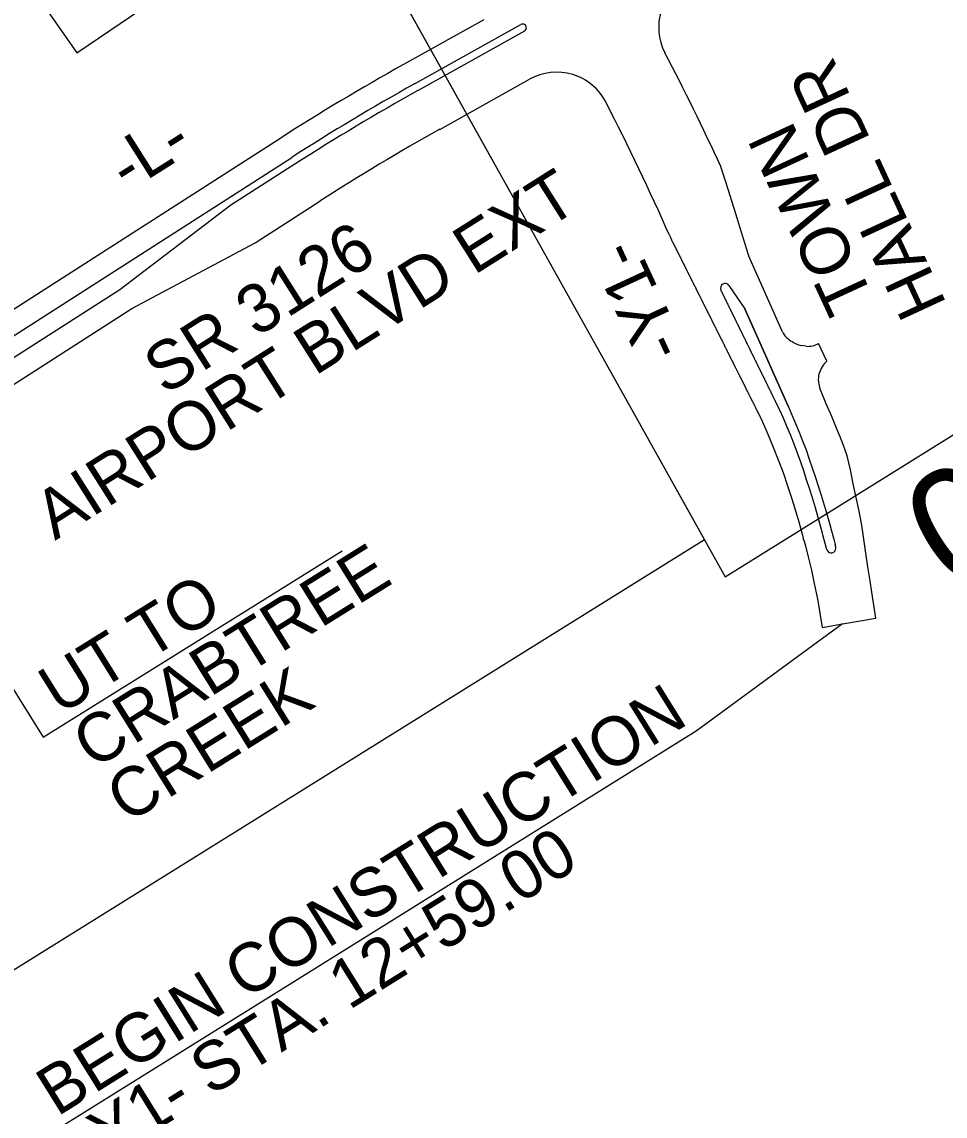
# Model space of a CAD drawing. Extents: x 2038094 to 2053858, y 751760 to 764312.
# Drawn here: x 2046894 to 2047889, y 757655 to 758834 of the extents above; entities that cross this region are included whole.
import ezdxf

# ---------------------------------------------------------------- set-up
doc = ezdxf.new("R2010")
doc.units = 0
for name, color, linetype in [('Old_Level_14', 7, 'Continuous'), ('Prop Shade Light', 7, 'Continuous'), ('Scratch_Level_1', 7, 'Continuous'), ('Sheet Data Field CELL', 7, 'Continuous')]:
    doc.layers.add(name, color=color, linetype=linetype)

msp = doc.modelspace()

# ---------------------------------------------------------------- linework, layer by layer
at = {"layer": 'Old_Level_14'}
for points in [[(2046826.6, 758207.9), (2046916.9, 758063.2), (2047239.3, 758264)], [(2047778.5, 758185.1), (2047620.9, 758069.4), (2046917.9, 757631.6)]]:
    msp.add_lwpolyline(points, dxfattribs=at)
at = {"layer": 'Prop Shade Light'}
for p, q in [((2047392, 758836.5), (2047305.4, 758788.2)), ((2047317.1, 758767.2), (2047431.9, 758831.3)), ((2047435.8, 758824.3), (2047321, 758760.2)), ((2047344.4, 758718.3), (2047441, 758772.3)), ((2047171.9, 758708.2), (2046658.7, 758379)), ((2046689.7, 758370.3), (2047184.9, 758688)), ((2047189.2, 758681.3), (2047119.4, 758636.5)), ((2047647.3, 758678.3), (2047647.3, 758678.3)), ((2047119.4, 758636.5), (2046999.6, 758545.4)), ((2047145.3, 758596.1), (2047215.1, 758640.9)), ((2047592.3, 758603.5), (2047594.2, 758599.1)), ((2047012.6, 758525.2), (2047145.3, 758596.1)), ((2047712, 758503.8), (2047677.6, 758581.5)), ((2046999.6, 758545.4), (2046700.5, 758353.5)), ((2047656.1, 758550), (2047673.2, 758524.8)), ((2046695.4, 758321.8), (2047012.6, 758525.2)), ((2047719.9, 758419.7), (2047673.2, 758524.8)), ((2047673.2, 758524.8), (2047719.9, 758419.7)), ((2047713.7, 758500.1), (2047712, 758503.8)), ((2047739.2, 758484.4), (2047733.6, 758485.3)), ((2047761.5, 758468.2), (2047752.7, 758487.3)), ((2047756.7, 758282.5), (2047757, 758283)), ((2047757.1, 758282.6), (2047756.7, 758282.5)), ((2047736.3, 758276.9), (2047736.3, 758276.9)), ((2047750.2, 758218.8), (2047751.6, 758211.8)), ((2047751.6, 758211.8), (2047751.9, 758209.9)), ((2047814.3, 758191.3), (2047810.1, 758219.4)), ((2047751.9, 758209.9), (2047752.3, 758207.7)), ((2047752.3, 758207.7), (2047752.3, 758207.7)), ((2047752.3, 758207.7), (2047756.6, 758181.3)), ((2047778.5, 758185.1), (2047814.3, 758191.3)), ((2047756.6, 758181.3), (2047778.5, 758185.1))]:
    msp.add_line(p, q, dxfattribs=at)
for points in [[(2047752.7, 758447.2), (2047753, 758452.3), (2047753.5, 758455.1)], [(2047755.5, 758435.5), (2047755.1, 758436.5), (2047753.8, 758440.6)], [(2047767.1, 758408.6), (2047761, 758422.5), (2047755.5, 758435.5)], [(2047757, 758283), (2047753.5, 758296), (2047749.3, 758310.4), (2047746.1, 758321.2), (2047742.9, 758331), (2047739.8, 758340.6), (2047736.7, 758350.1), (2047733.5, 758359.6), (2047730, 758369.3), (2047726.4, 758378.9), (2047722.7, 758388.2), (2047718.8, 758397.4), (2047714.8, 758406.8), (2047710.8, 758415.7)], [(2047719.9, 758419.7), (2047724, 758410.6), (2047728, 758401.1), (2047731.9, 758391.9), (2047735.5, 758382.5), (2047739.2, 758372.7), (2047742.7, 758362.8), (2047746, 758353.3), (2047749.2, 758343.9), (2047752.3, 758334.1), (2047755.5, 758324), (2047758.8, 758313.2), (2047763, 758298.8), (2047764.2, 758294.7), (2047765.2, 758291), (2047766.8, 758285.4)], [(2047690.5, 758406.9), (2047692.2, 758402.9), (2047698, 758389.5), (2047703.8, 758375.7), (2047709.3, 758362), (2047714.4, 758348.2), (2047719.2, 758334), (2047723.8, 758319.8), (2047728.3, 758305.8), (2047731.5, 758295.1), (2047735.3, 758280.8), (2047736.3, 758277.3), (2047736.3, 758276.9)], [(2047775.9, 758386.8), (2047772.9, 758394.4), (2047767.1, 758408.6)], [(2047781.3, 758372.5), (2047779.6, 758377.4), (2047775.9, 758386.8)], [(2047793.3, 758321.5), (2047790.1, 758336.3), (2047787, 758351.1), (2047783.4, 758366.2), (2047781.3, 758372.5)], [(2047803.8, 758261.5), (2047801.6, 758276.6), (2047799.3, 758291.6), (2047796.4, 758306.5), (2047793.3, 758321.5)], [(2047761.7, 758265.1), (2047761.2, 758266.5), (2047757.5, 758281.1), (2047757.1, 758282.6)], [(2047766.8, 758285.4), (2047769.1, 758276.4), (2047770.6, 758270.9)], [(2047736.3, 758276.9), (2047737.1, 758274.3), (2047738.5, 758269.3), (2047741.5, 758257.4)], [(2047810.1, 758219.4), (2047808.3, 758231.6), (2047806, 758246.5), (2047803.8, 758261.5)], [(2047741.5, 758257.4), (2047745, 758243), (2047748.1, 758228.7), (2047750.2, 758218.8)]]:
    msp.add_lwpolyline(points, dxfattribs=at)
for centre, radius, start, end in [((2047640.4, 758828.5), 60, 119.1633, 207.4145), ((2047433.8, 758827.8), 4, 299.1633, 119.1633), ((2044880.6, 757397.1), 3049, 24.8477, 27.4145), ((2048540.2, 756575.4), 2534, 119.1633, 122.6814), ((2047470.3, 758719.9), 60, 27.0571, 119.1633), ((2048540.2, 756575.4), 2510, 119.1633, 122.6814), ((2048540.2, 756575.4), 2502, 119.1633, 122.6814), ((2044880.6, 757397.1), 2968, 23.9842, 27.0571), ((2048540.2, 756575.4), 2454, 119.1633, 122.6814), ((2047652, 758547.2), 5, 34.1532, 206.1151)]:
    msp.add_arc(centre, radius, start, end, dxfattribs=at)
for centre, major_axis, ratio, start_param, end_param in [((2047736.6, 758512.2), (15.6, -20.7), 0.999438, 4.55283, 5.136828), ((2047741, 758515.2), (28.5, -11.7), 0.998991, 4.52143, 4.859942), ((2047740.9, 758509.4), (25, -1.8), 0.999784, 4.715604, 5.276431), ((2047779.9, 758447.8), (-0.3, -27.5), 0.999465, 3.886167, 4.451924), ((2047771.8, 758447), (3.2, -18.9), 0.997089, 4.537364, 4.888286), ((2047757.6, 758266.6), (-7.1, 11.7), 0.995989, 4.19904, 4.490773), ((2047766.4, 758266.5), (3.25, -3.72), 0.998575, 4.2934, 7.2349)]:
    msp.add_ellipse(centre, major_axis=major_axis, ratio=ratio, start_param=start_param, end_param=end_param, dxfattribs=at)
for points in [[(2047652.6, 758662.1), (2047652.4, 758662.5), (2047652.2, 758663.2), (2047652, 758663.8), (2047651.8, 758664.5), (2047651.6, 758665.1), (2047651.4, 758665.8), (2047651.1, 758666.5), (2047650.9, 758667.1), (2047650.7, 758667.8), (2047650.5, 758668.4), (2047650.3, 758669.1), (2047650.1, 758669.8), (2047649.9, 758670.4), (2047649.7, 758671.1), (2047649.4, 758671.7), (2047649.2, 758672.4), (2047649, 758673), (2047648.8, 758673.7), (2047648.6, 758674.4), (2047648.4, 758675), (2047648.2, 758675.7), (2047647.9, 758676.3), (2047647.7, 758677), (2047647.3, 758678.3)], [(2047657.7, 758645.9), (2047657.7, 758646.1), (2047657.4, 758646.7), (2047657.2, 758647.4), (2047657, 758648), (2047656.8, 758648.7), (2047656.6, 758649.4), (2047656.4, 758650), (2047656.2, 758650.7), (2047656, 758651.3), (2047655.8, 758652), (2047655.6, 758652.6), (2047655.4, 758653.3), (2047655.2, 758654), (2047654.9, 758654.6), (2047654.7, 758655.3), (2047654.5, 758655.9), (2047654.3, 758656.6), (2047654.1, 758657.3), (2047653.9, 758657.9), (2047653.7, 758658.6), (2047653.5, 758659.2), (2047653.3, 758659.9), (2047653.1, 758660.5), (2047652.8, 758661.2), (2047652.6, 758661.9), (2047652.6, 758662.1)], [(2047662.8, 758629.6), (2047662.6, 758630.3), (2047662.4, 758630.9), (2047662.2, 758631.6), (2047662, 758632.2), (2047661.8, 758632.9), (2047661.6, 758633.5), (2047661.4, 758634.2), (2047661.2, 758634.9), (2047661, 758635.5), (2047660.7, 758636.2), (2047660.5, 758636.8), (2047660.3, 758637.5), (2047660.1, 758638.2), (2047659.9, 758638.8), (2047659.7, 758639.5), (2047659.5, 758640.1), (2047659.3, 758640.8), (2047659.1, 758641.4), (2047658.9, 758642.1), (2047658.7, 758642.8), (2047658.5, 758643.4), (2047658.3, 758644.1), (2047658.1, 758644.7), (2047657.9, 758645.4), (2047657.7, 758645.9)], [(2047667.7, 758613.6), (2047667.6, 758614), (2047667.4, 758614.7), (2047667.2, 758615.3), (2047667, 758616), (2047666.8, 758616.6), (2047666.6, 758617.3), (2047666.4, 758617.9), (2047666.2, 758618.6), (2047666, 758619.2), (2047665.8, 758619.9), (2047665.6, 758620.5), (2047665.4, 758621.2), (2047665.2, 758621.8), (2047665, 758622.5), (2047664.8, 758623.1), (2047664.6, 758623.8), (2047664.4, 758624.4), (2047664.2, 758625.1), (2047664, 758625.7), (2047663.8, 758626.4), (2047663.6, 758627), (2047663.4, 758627.7), (2047663.2, 758628.3), (2047663, 758629), (2047662.8, 758629.6)], [(2047672.7, 758597.5), (2047672.6, 758597.8), (2047672.4, 758598.4), (2047672.2, 758599.1), (2047672, 758599.7), (2047671.8, 758600.4), (2047671.6, 758601), (2047671.4, 758601.7), (2047671.2, 758602.3), (2047671, 758603), (2047670.8, 758603.6), (2047670.6, 758604.3), (2047670.4, 758604.9), (2047670.2, 758605.6), (2047670, 758606.2), (2047669.8, 758606.9), (2047669.6, 758607.5), (2047669.4, 758608.2), (2047669.2, 758608.8), (2047669, 758609.5), (2047668.8, 758610.1), (2047668.6, 758610.8), (2047668.4, 758611.4), (2047668.2, 758612.1), (2047668, 758612.7), (2047667.8, 758613.4), (2047667.7, 758613.6)], [(2047594.2, 758599.1), (2047595.1, 758597.4), (2047595.6, 758596.5), (2047596, 758595.7), (2047596.4, 758594.8), (2047596.9, 758593.9), (2047597.3, 758593.1), (2047597.7, 758592.2), (2047598.2, 758591.3), (2047598.6, 758590.5), (2047599, 758589.6), (2047599.5, 758588.7), (2047599.9, 758587.9), (2047600.3, 758587), (2047600.8, 758586.1), (2047601.2, 758585.3), (2047601.6, 758584.4), (2047602.1, 758583.5), (2047602.5, 758582.6), (2047602.9, 758581.8), (2047603.4, 758580.9), (2047603.8, 758580), (2047604.2, 758579.2), (2047604.7, 758578.3), (2047605, 758577.7)], [(2047677.6, 758581.5), (2047677.4, 758582.2), (2047677.2, 758582.8), (2047677, 758583.5), (2047676.8, 758584.1), (2047676.6, 758584.8), (2047676.4, 758585.4), (2047676.2, 758586.1), (2047676, 758586.7), (2047675.8, 758587.4), (2047675.6, 758588), (2047675.4, 758588.7), (2047675.2, 758589.3), (2047675, 758590), (2047674.8, 758590.6), (2047674.6, 758591.3), (2047674.4, 758591.9), (2047674.2, 758592.6), (2047674, 758593.2), (2047673.8, 758593.9), (2047673.6, 758594.5), (2047673.4, 758595.2), (2047673.2, 758595.8), (2047673, 758596.5), (2047672.8, 758597.1), (2047672.7, 758597.5)], [(2047605, 758577.7), (2047605.1, 758577.4), (2047605.5, 758576.6), (2047606, 758575.7), (2047606.4, 758574.8), (2047606.8, 758574), (2047607.3, 758573.1), (2047607.7, 758572.2), (2047608.1, 758571.4), (2047608.6, 758570.5), (2047609, 758569.6), (2047609.4, 758568.8), (2047609.9, 758567.9), (2047610.3, 758567), (2047610.7, 758566.2), (2047611.2, 758565.3), (2047611.6, 758564.4), (2047612, 758563.6), (2047612.5, 758562.7), (2047612.9, 758561.8), (2047613.3, 758561), (2047613.8, 758560.1), (2047614.2, 758559.2), (2047614.6, 758558.4), (2047615.1, 758557.5), (2047615.5, 758556.6), (2047615.7, 758556.4)], [(2047615.7, 758556.4), (2047615.9, 758555.8), (2047616.4, 758554.9), (2047616.8, 758554), (2047617.2, 758553.2), (2047617.7, 758552.3), (2047618.1, 758551.4), (2047618.6, 758550.6), (2047619, 758549.7), (2047619.4, 758548.8), (2047619.9, 758548), (2047620.3, 758547.1), (2047620.7, 758546.2), (2047621.2, 758545.4), (2047621.6, 758544.5), (2047622, 758543.6), (2047622.5, 758542.8), (2047622.9, 758541.9), (2047623.3, 758541), (2047623.8, 758540.2), (2047624.2, 758539.3), (2047624.6, 758538.4), (2047625.1, 758537.6), (2047625.5, 758536.7), (2047625.9, 758535.8), (2047626.4, 758535)], [(2047658.1, 758523.3), (2047658, 758523.6), (2047657.6, 758524.5), (2047657.1, 758525.3), (2047656.7, 758526.2), (2047656.3, 758527.1), (2047655.9, 758527.9), (2047655.4, 758528.8), (2047655, 758529.7), (2047654.6, 758530.6), (2047654.1, 758531.4), (2047653.7, 758532.3), (2047653.3, 758533.2), (2047652.9, 758534), (2047652.4, 758534.9), (2047652, 758535.8), (2047651.6, 758536.7), (2047651.2, 758537.5), (2047650.7, 758538.4), (2047650.3, 758539.3), (2047649.9, 758540.1), (2047649.5, 758541), (2047649, 758541.9), (2047648.6, 758542.7), (2047648.2, 758543.6), (2047647.5, 758545)], [(2047626.4, 758535), (2047626.8, 758534.1), (2047627.2, 758533.2), (2047627.7, 758532.4), (2047628.1, 758531.5), (2047628.5, 758530.6), (2047629, 758529.8), (2047629.4, 758528.9), (2047629.8, 758528), (2047630.3, 758527.2), (2047630.7, 758526.3), (2047631.1, 758525.4), (2047631.6, 758524.6), (2047632, 758523.7), (2047632.4, 758522.8), (2047632.9, 758522), (2047633.3, 758521.1), (2047633.7, 758520.2), (2047634.2, 758519.4), (2047634.6, 758518.5), (2047635, 758517.6), (2047635.5, 758516.8), (2047635.9, 758515.9), (2047636.3, 758515), (2047636.8, 758514.2), (2047637.1, 758513.6)], [(2047668.7, 758501.7), (2047668.6, 758501.8), (2047668.2, 758502.7), (2047667.8, 758503.6), (2047667.4, 758504.5), (2047666.9, 758505.3), (2047666.5, 758506.2), (2047666.1, 758507.1), (2047665.7, 758507.9), (2047665.2, 758508.8), (2047664.8, 758509.7), (2047664.4, 758510.5), (2047664, 758511.4), (2047663.5, 758512.3), (2047663.1, 758513.2), (2047662.7, 758514), (2047662.3, 758514.9), (2047661.8, 758515.8), (2047661.4, 758516.6), (2047661, 758517.5), (2047660.5, 758518.4), (2047660.1, 758519.2), (2047659.7, 758520.1), (2047659.3, 758521), (2047658.8, 758521.9), (2047658.4, 758522.7), (2047658.1, 758523.3)], [(2047637.1, 758513.6), (2047637.2, 758513.3), (2047637.6, 758512.4), (2047638.1, 758511.6), (2047638.5, 758510.7), (2047638.9, 758509.8), (2047639.4, 758509), (2047639.8, 758508.1), (2047640.2, 758507.2), (2047640.7, 758506.4), (2047641.1, 758505.5), (2047641.5, 758504.6), (2047642, 758503.8), (2047642.4, 758502.9), (2047642.8, 758502), (2047643.3, 758501.2), (2047643.7, 758500.3), (2047644.2, 758499.4), (2047644.6, 758498.6), (2047645, 758497.7), (2047645.5, 758496.8), (2047645.9, 758496), (2047646.3, 758495.1), (2047646.8, 758494.2), (2047647.2, 758493.4), (2047647.6, 758492.5), (2047647.8, 758492.2)], [(2047679.3, 758480.1), (2047678.9, 758481), (2047678.5, 758481.8), (2047678, 758482.7), (2047677.6, 758483.6), (2047677.2, 758484.4), (2047676.8, 758485.3), (2047676.3, 758486.2), (2047675.9, 758487), (2047675.5, 758487.9), (2047675, 758488.8), (2047674.6, 758489.7), (2047674.2, 758490.5), (2047673.8, 758491.4), (2047673.3, 758492.3), (2047672.9, 758493.1), (2047672.5, 758494), (2047672.1, 758494.9), (2047671.6, 758495.8), (2047671.2, 758496.6), (2047670.8, 758497.5), (2047670.4, 758498.4), (2047669.9, 758499.2), (2047669.5, 758500.1), (2047669.1, 758501), (2047668.7, 758501.7)], [(2047647.8, 758492.2), (2047648.1, 758491.6), (2047648.5, 758490.8), (2047648.9, 758489.9), (2047649.4, 758489), (2047649.8, 758488.2), (2047650.2, 758487.3), (2047650.7, 758486.4), (2047651.1, 758485.6), (2047651.5, 758484.7), (2047652, 758483.8), (2047652.4, 758483), (2047652.8, 758482.1), (2047653.3, 758481.2), (2047653.7, 758480.4), (2047654.1, 758479.5), (2047654.6, 758478.6), (2047655, 758477.7), (2047655.4, 758476.9), (2047655.9, 758476), (2047656.3, 758475.1), (2047656.7, 758474.3), (2047657.2, 758473.4), (2047657.6, 758472.5), (2047658, 758471.7), (2047658.5, 758470.8)], [(2047658.5, 758470.8), (2047658.9, 758469.9), (2047659.3, 758469.1), (2047659.8, 758468.2), (2047660.2, 758467.3), (2047660.6, 758466.5), (2047661.1, 758465.6), (2047661.5, 758464.7), (2047661.9, 758463.9), (2047662.4, 758463), (2047662.8, 758462.1), (2047663.2, 758461.3), (2047663.7, 758460.4), (2047664.1, 758459.5), (2047664.5, 758458.7), (2047665, 758457.8), (2047665.4, 758456.9), (2047665.8, 758456.1), (2047666.3, 758455.2), (2047666.7, 758454.3), (2047667.1, 758453.5), (2047667.6, 758452.6), (2047668, 758451.7), (2047668.5, 758450.9), (2047668.9, 758450), (2047669.1, 758449.5)], [(2047689.8, 758458.6), (2047689.6, 758459.2), (2047689.1, 758460.1), (2047688.7, 758460.9), (2047688.3, 758461.8), (2047687.8, 758462.7), (2047687.4, 758463.6), (2047687, 758464.4), (2047686.6, 758465.3), (2047686.1, 758466.2), (2047685.7, 758467), (2047685.3, 758467.9), (2047684.9, 758468.8), (2047684.4, 758469.6), (2047684, 758470.5), (2047683.6, 758471.4), (2047683.2, 758472.3), (2047682.7, 758473.1), (2047682.3, 758474), (2047681.9, 758474.9), (2047681.4, 758475.7), (2047681, 758476.6), (2047680.6, 758477.5), (2047680.2, 758478.3), (2047679.7, 758479.2), (2047679.3, 758480.1)], [(2047669.1, 758449.5), (2047669.3, 758449.1), (2047669.8, 758448.3), (2047670.2, 758447.4), (2047670.6, 758446.5), (2047671.1, 758445.7), (2047671.5, 758444.8), (2047671.9, 758443.9), (2047672.4, 758443.1), (2047672.8, 758442.2), (2047673.2, 758441.3), (2047673.7, 758440.5), (2047674.1, 758439.6), (2047674.5, 758438.7), (2047675, 758437.9), (2047675.4, 758437), (2047675.8, 758436.1), (2047676.3, 758435.3), (2047676.7, 758434.4), (2047677.1, 758433.5), (2047677.6, 758432.7), (2047678, 758431.8), (2047678.4, 758430.9), (2047678.9, 758430.1), (2047679.3, 758429.2), (2047679.7, 758428.3), (2047679.8, 758428.2)], [(2047700.4, 758437.2), (2047700.2, 758437.4), (2047699.8, 758438.3), (2047699.4, 758439.2), (2047698.9, 758440.1), (2047698.5, 758440.9), (2047698.1, 758441.8), (2047697.7, 758442.7), (2047697.2, 758443.5), (2047696.8, 758444.4), (2047696.4, 758445.3), (2047696, 758446.1), (2047695.5, 758447), (2047695.1, 758447.9), (2047694.7, 758448.8), (2047694.2, 758449.6), (2047693.8, 758450.5), (2047693.4, 758451.4), (2047693, 758452.2), (2047692.5, 758453.1), (2047692.1, 758454), (2047691.7, 758454.9), (2047691.3, 758455.7), (2047690.8, 758456.6), (2047690.4, 758457.5), (2047690, 758458.3), (2047689.8, 758458.6)], [(2047710.8, 758415.7), (2047710.5, 758416.6), (2047710, 758417.4), (2047709.6, 758418.3), (2047709.2, 758419.2), (2047708.7, 758420), (2047708.3, 758420.9), (2047707.9, 758421.8), (2047707.5, 758422.7), (2047707, 758423.5), (2047706.6, 758424.4), (2047706.2, 758425.3), (2047705.8, 758426.1), (2047705.3, 758427), (2047704.9, 758427.9), (2047704.5, 758428.7), (2047704.1, 758429.6), (2047703.6, 758430.5), (2047703.2, 758431.4), (2047702.8, 758432.2), (2047702.3, 758433.1), (2047701.9, 758434), (2047701.5, 758434.8), (2047701.1, 758435.7), (2047700.6, 758436.6), (2047700.4, 758437.2)], [(2047679.8, 758428.2), (2047680.2, 758427.5), (2047680.6, 758426.6), (2047681, 758425.7), (2047681.5, 758424.9), (2047681.9, 758424), (2047682.3, 758423.1), (2047682.8, 758422.3), (2047683.2, 758421.4), (2047683.6, 758420.5), (2047684.1, 758419.7), (2047684.5, 758418.8), (2047684.9, 758417.9), (2047685.4, 758417.1), (2047685.8, 758416.2), (2047686.2, 758415.3), (2047686.7, 758414.5), (2047687.1, 758413.6), (2047687.5, 758412.7), (2047688, 758411.9), (2047688.4, 758411), (2047688.8, 758410.1), (2047689.3, 758409.3), (2047689.7, 758408.4), (2047690.1, 758407.5), (2047690.5, 758406.9)]]:
    msp.add_spline(points, degree=3, dxfattribs=at)
at = {"layer": 'Scratch_Level_1'}
for points in [[(2046953.3, 758800.9), (2047822.7, 759389.8), (2047107.6, 760411.3), (2046421.2, 759929.6), (2046541.4, 759758.3), (2046449.6, 759694), (2046540.4, 759564.6), (2046459, 759507.5)], [(2047231.5, 758989.4), (2047651.9, 758235.9), (2048432.2, 758721.8), (2048320.7, 758901.4), (2048734.5, 759088.9), (2048387.9, 759645.5), (2047820.9, 759388.6)], [(2045946.3, 758464.5), (2046501.4, 757573.2), (2047629.6, 758276), (2047220.5, 759009), (2047136.3, 758956.5), (2047077, 759051.7), (2046934.2, 758962.7), (2046881.6, 759047.1)]]:
    msp.add_lwpolyline(points, close=True, dxfattribs=at)

# ---------------------------------------------------------------- texts
at = {"layer": 'Old_Level_14'}
for s, height, p in [('CRABTREE ', 52.5, (2046971, 758027.5)), ('UT TO ', 52.5, (2046934.6, 758086)), ('CREEK', 52.5, (2047007.4, 757969.1)), ('BEGIN CONSTRUCTION', 52.501, (2046932, 757653.4)), ('-Y1- STA. 12+59.00', 52.501, (2046968.4, 757595))]:
    msp.add_text(s, height=height, rotation=31.918, dxfattribs=at).set_placement(p)
at = {"layer": 'Scratch_Level_1'}
msp.add_text('05', height=125, rotation=31.918, dxfattribs=at).set_placement((2047898.9, 758214.6))
at = {"layer": 'Sheet Data Field CELL'}
for s, height, rotation, p in [('HALL DR', 52.5, 114.8311, (2047891.3, 758529.6)), ('TOWN ', 52.5, 114.8311, (2047813, 758534.9)), ('-L-', 52.5, 32.3416, (2047008.1, 758650.1)), ('AIRPORT BLVD EXT', 52.501, 32.3416, (2046929.7, 758274.6)), ('SR 3126', 52.5, 32.3416, (2047048, 758431)), ('-Y1-', 52.5, 114.8311, (2047609.7, 758482.6))]:
    msp.add_text(s, height=height, rotation=rotation, dxfattribs=at).set_placement(p)

doc.saveas('drawing.dxf')
